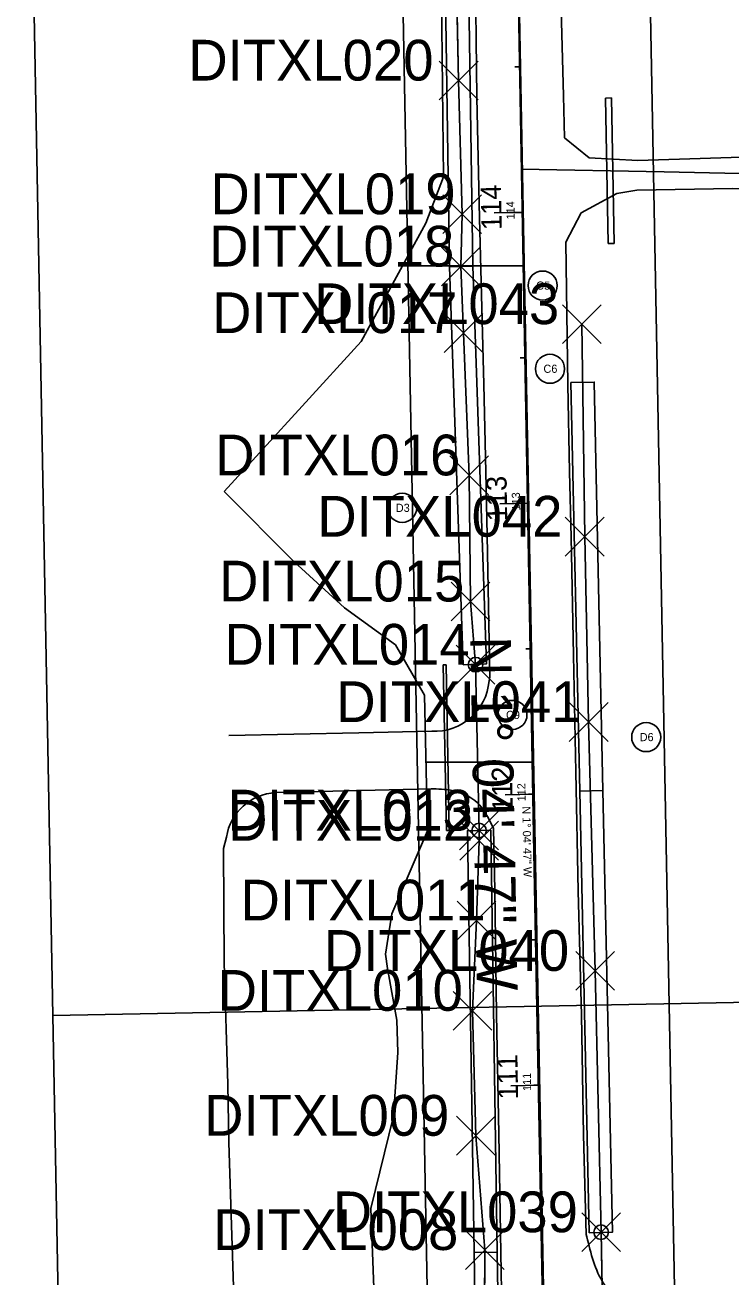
# Model space of a CAD drawing. Extents: x 2287043 to 2296348, y 637947 to 641293.
# Drawn here: x 2287203.9 to 2287446.6, y 639007.3 to 639437.5 of the extents above; entities that cross this region are included whole.
import ezdxf

# ---------------------------------------------------------------- set-up
doc = ezdxf.new("R2010")
doc.units = 0
for name, color, linetype in [('DR_P_Drainage_Area', 7, 'Continuous'), ('DR_P_Storm_Sewer', 7, 'Continuous'), ('GE_X_CL_100', 7, 'Continuous'), ('GE_X_CL_20', 7, 'Continuous'), ('GE_X_CL_50', 7, 'Continuous'), ('GK_Visualization', 7, 'Continuous'), ('RW_P_Prelim_RW', 7, 'Continuous'), ('SC_Scratch11', 7, 'Continuous'), ('SC_Scratch12', 7, 'Continuous'), ('SC_Scratch2', 7, 'Continuous'), ('SC_Scratch4', 7, 'Continuous'), ('SC_Scratch7', 7, 'Continuous'), ('SC_Scratch8', 7, 'Continuous'), ('SC_Scratch9', 7, 'Continuous')]:
    doc.layers.add(name, color=color, linetype=linetype)

msp = doc.modelspace()

# ---------------------------------------------------------------- linework, layer by layer
at = {"layer": 'DR_P_Drainage_Area'}
for p, q in [((2287344.62, 639663.86), (2287347.81, 639385.32)), ((2287378.24, 639184.24), (2287341.77, 639184.24)), ((2287327.5, 638898.94), (2287322.85, 639030.76))]:
    msp.add_line(p, q, dxfattribs=at)
for points in [[(2287365.99, 639861.68), (2287378.81, 639153.12), (2287391.95, 638476.45)], [(2287374.46, 639387.93), (2287423.69, 639387.1), (2287491.39, 639385.61), (2287561.27, 639386.88)], [(2287347.81, 639385.32), (2287341.65, 639369.4), (2287319.48, 639328.73), (2287299.16, 639306.57), (2287272.39, 639277.21)], [(2287331.33, 639224.47), (2287313.69, 639237.21), (2287296.31, 639253.19), (2287272.39, 639277.21)], [(2287342.24, 639160.62), (2287341.3, 639207.22), (2287331.33, 639224.47)], [(2287327.88, 639118.25), (2287330.07, 639132.12), (2287342.24, 639160.62)], [(2287322.85, 639030.76), (2287330.55, 639062.49), (2287332.11, 639084.39), (2287331.79, 639095.57), (2287328.48, 639113.22), (2287327.88, 639118.25)]]:
    msp.add_lwpolyline(points, dxfattribs=at)
at = {"layer": 'DR_P_Storm_Sewer'}
for p, q in [((2287403.48, 639412.42), (2287405.48, 639412.45)), ((2287404.43, 639362.43), (2287403.48, 639412.42)), ((2287406.43, 639362.46), (2287405.48, 639412.45)), ((2287404.43, 639362.43), (2287406.43, 639362.46)), ((2287347.69, 639217.66), (2287348.69, 639217.68)), ((2287348.76, 639160.68), (2287347.69, 639217.66)), ((2287349.76, 639160.7), (2287348.69, 639217.68)), ((2287348.76, 639160.68), (2287349.76, 639160.7))]:
    msp.add_line(p, q, dxfattribs=at)
at = {"layer": 'GE_X_CL_100'}
for p, q in [((2287401.6, 637973.38), (2287357.08, 640335.42)), ((2287375.22, 639373.13), (2287365.22, 639372.94)), ((2287377.1, 639273.15), (2287367.1, 639272.96)), ((2287378.99, 639173.17), (2287368.99, 639172.98)), ((2287380.87, 639073.19), (2287370.87, 639073))]:
    msp.add_line(p, q, dxfattribs=at)
at = {"layer": 'GE_X_CL_20'}
for p, q in [((2287401.6, 637973.38), (2287357.08, 640335.42)), ((2287374.28, 639423.12), (2287372.28, 639423.09)), ((2287375.22, 639373.13), (2287373.22, 639373.1)), ((2287376.16, 639323.14), (2287374.16, 639323.1)), ((2287377.1, 639273.15), (2287375.1, 639273.11)), ((2287378.05, 639223.16), (2287376.05, 639223.12)), ((2287378.99, 639173.17), (2287376.99, 639173.13)), ((2287379.93, 639123.18), (2287377.93, 639123.14)), ((2287380.87, 639073.19), (2287378.87, 639073.15)), ((2287381.81, 639023.2), (2287379.81, 639023.16))]:
    msp.add_line(p, q, dxfattribs=at)
at = {"layer": 'GE_X_CL_50'}
for p, q in [((2287401.6, 637973.38), (2287357.08, 640335.42)), ((2287375.22, 639373.13), (2287370.22, 639373.04)), ((2287375.22, 639373.13), (2287370.22, 639373.04)), ((2287377.1, 639273.15), (2287372.1, 639273.06)), ((2287377.1, 639273.15), (2287372.1, 639273.06)), ((2287378.99, 639173.17), (2287373.99, 639173.07)), ((2287378.99, 639173.17), (2287373.99, 639173.07)), ((2287380.87, 639073.19), (2287375.87, 639073.09)), ((2287380.87, 639073.19), (2287375.87, 639073.09))]:
    msp.add_line(p, q, dxfattribs=at)
at = {"layer": 'GK_Visualization'}
for p, q in [((2287352.98, 639418.42), (2287351.79, 639473.08)), ((2287346.31, 639411.75), (2287359.65, 639425.1)), ((2287346.31, 639425.1), (2287359.65, 639411.75)), ((2287354.17, 639372.48), (2287352.98, 639418.42)), ((2287347.5, 639365.81), (2287360.83, 639379.16)), ((2287347.5, 639379.16), (2287360.83, 639365.81)), ((2287353.72, 639354.51), (2287354.17, 639372.48)), ((2287347.05, 639347.84), (2287360.38, 639361.19)), ((2287347.05, 639361.19), (2287360.38, 639347.84)), ((2287354.63, 639331.64), (2287353.72, 639354.51)), ((2287388.64, 639328.04), (2287401.97, 639341.39)), ((2287388.64, 639341.39), (2287401.97, 639328.04)), ((2287347.96, 639324.97), (2287361.29, 639338.32)), ((2287347.96, 639338.32), (2287361.29, 639324.97)), ((2287356.58, 639282.73), (2287354.63, 639331.64)), ((2287396.32, 639261.68), (2287395.31, 639334.71)), ((2287349.91, 639276.06), (2287363.25, 639289.41)), ((2287349.91, 639289.41), (2287363.25, 639276.06)), ((2287357.05, 639239.4), (2287356.58, 639282.73)), ((2287389.65, 639255), (2287402.99, 639268.35)), ((2287389.65, 639268.35), (2287402.99, 639255)), ((2287397.68, 639197.97), (2287396.32, 639261.68)), ((2287350.38, 639232.73), (2287363.71, 639246.08)), ((2287350.38, 639246.08), (2287363.71, 639232.73)), ((2287358.79, 639217.68), (2287357.05, 639239.4)), ((2287352.13, 639211.01), (2287365.46, 639224.36)), ((2287352.13, 639224.36), (2287365.46, 639211.01)), ((2287360, 639160.7), (2287358.79, 639217.68)), ((2287391.01, 639191.29), (2287404.35, 639204.64)), ((2287391.01, 639204.64), (2287404.35, 639191.29)), ((2287399.93, 639112.47), (2287397.68, 639197.97)), ((2287353.33, 639154.03), (2287366.66, 639167.38)), ((2287353.33, 639167.38), (2287366.66, 639154.03)), ((2287353.39, 639150.51), (2287366.72, 639163.86)), ((2287353.39, 639163.86), (2287366.72, 639150.51)), ((2287360.05, 639157.19), (2287360, 639160.7)), ((2287359.14, 639129.78), (2287360.05, 639157.19)), ((2287352.47, 639123.11), (2287365.81, 639136.46)), ((2287352.47, 639136.46), (2287365.81, 639123.11)), ((2287357.77, 639098.75), (2287359.14, 639129.78)), ((2287393.26, 639105.8), (2287406.6, 639119.15)), ((2287393.26, 639119.15), (2287406.6, 639105.8)), ((2287401.96, 639022.65), (2287399.93, 639112.47)), ((2287351.1, 639092.08), (2287364.44, 639105.43)), ((2287351.1, 639105.43), (2287364.44, 639092.08)), ((2287358.87, 639055.82), (2287357.77, 639098.75)), ((2287352.2, 639049.15), (2287365.53, 639062.5)), ((2287352.2, 639062.5), (2287365.53, 639049.15)), ((2287361.96, 639016.55), (2287358.87, 639055.82)), ((2287395.3, 639015.97), (2287408.63, 639029.32)), ((2287395.3, 639029.32), (2287408.63, 639015.97)), ((2287355.29, 639009.87), (2287368.62, 639023.22)), ((2287355.29, 639023.22), (2287368.62, 639009.87)), ((2287403.46, 638936.65), (2287401.96, 639022.65)), ((2287361.74, 638970.54), (2287361.96, 639016.55))]:
    msp.add_line(p, q, dxfattribs=at)
at = {"layer": 'RW_P_Prelim_RW'}
for p, q in [((2287348.42, 638672.5), (2287326.8, 639819.59)), ((2287433.4, 638674.11), (2287411.84, 639818.25))]:
    msp.add_line(p, q, dxfattribs=at)
at = {"layer": 'SC_Scratch11'}
for points in [[(2287349.86, 639354.56), (2287342.67, 639840.38), (2287350.67, 639840.5), (2287357.86, 639354.68)], [(2287354.57, 639217.68), (2287349.86, 639354.41), (2287357.86, 639354.68), (2287362.56, 639217.96)], [(2287394.6, 639174.25), (2287391.58, 639314.63), (2287399.58, 639314.8), (2287402.6, 639174.42)], [(2287358.28, 639015.66), (2287356, 639160.64), (2287364, 639160.76), (2287366.28, 639015.78)]]:
    msp.add_lwpolyline(points, close=True, dxfattribs=at)
at = {"layer": 'SC_Scratch12'}
msp.add_line((2287375.16, 639354.77), (2287333.67, 639354.77), dxfattribs=at)
at = {"layer": 'SC_Scratch2'}
for points in [[(2287213.53, 639097.15), (2287203.92, 639607.06), (2287533.86, 639613.28), (2287543.47, 639103.37)], [(2287223.14, 638587.24), (2287213.53, 639097.15), (2287543.47, 639103.37), (2287553.08, 638593.46)]]:
    msp.add_lwpolyline(points, close=True, dxfattribs=at)
at = {"layer": 'SC_Scratch4'}
for p, q in [((2287363.72, 639213.43), (2287363.42, 639212.08)), ((2287290.08, 639173.71), (2287314.69, 639174.36)), ((2287314.69, 639174.36), (2287343.52, 639175.02)), ((2287364.53, 639162.41), (2287364.94, 639161.35)), ((2287272.17, 639154.51), (2287273.16, 639158.41)), ((2287396.86, 639021.86), (2287397.08, 639021.08))]:
    msp.add_line(p, q, dxfattribs=at)
for points in [[(2287362.77, 639262.13), (2287362.38, 639283.92), (2287361.7, 639313.93), (2287360.11, 639371.1), (2287359.2, 639412.59), (2287358.64, 639462.65), (2287357.69, 639512.4), (2287356.88, 639563.05), (2287355.9, 639612.32)], [(2287385.25, 639612.29), (2287386.09, 639563.69), (2287386.86, 639511.87), (2287387.65, 639464.13), (2287388.98, 639413.19), (2287389.34, 639398.71)], [(2287414.56, 639390.91), (2287397.81, 639391.91), (2287389.34, 639398.71)], [(2287414.56, 639390.91), (2287464.55, 639392.5), (2287481.49, 639391.88), (2287499.77, 639391.8), (2287508.6, 639391.91), (2287533.21, 639392.12), (2287559.37, 639392.76)], [(2287389.84, 639362.89), (2287395.12, 639372.95), (2287407.35, 639379.58), (2287414.26, 639380.77)], [(2287484.85, 639380.5), (2287472.49, 639380.96), (2287447.25, 639381.27), (2287414.26, 639380.77)], [(2287389.84, 639362.89), (2287390.55, 639314), (2287391.1, 639283.94), (2287391.72, 639261.53)], [(2287362.77, 639262.13), (2287363.72, 639213.43)], [(2287391.72, 639261.53), (2287392.47, 639220.98), (2287393.32, 639180.85), (2287394.08, 639139.83), (2287395.22, 639097.24), (2287395.88, 639056.14), (2287396.86, 639021.86)], [(2287343.76, 639194.79), (2287318.71, 639194.3), (2287273.95, 639193.4)], [(2287364.94, 639161.35), (2287365.38, 639140.22), (2287366.04, 639097.42), (2287366.85, 639056.45), (2287367.51, 639015.53), (2287368.23, 638976.63), (2287368.94, 638936.33), (2287369.74, 638895.15), (2287370.39, 638855.41), (2287370.66, 638843.13)], [(2287272.17, 639154.51), (2287272.32, 639115.21), (2287273.58, 639073.5)], [(2287277.68, 638935.54), (2287277.57, 638940.74), (2287276.27, 638982.52), (2287273.98, 639053.49), (2287273.58, 639073.5)]]:
    msp.add_lwpolyline(points, dxfattribs=at)
for centre, radius, start, end in [((2287344.69, 639213.56), 18.79, 267.1606, 355.5044), ((2287291.04, 639155.65), 18.09, 93.0457, 171.2442)]:
    msp.add_arc(centre, radius, start, end, dxfattribs=at)
for points in [[(2287343.52, 639175.02), (2287350.65, 639174.47), (2287359.42, 639170.18), (2287364.53, 639162.41)], [(2287397.08, 639021.08), (2287402.95, 639004.87), (2287413, 638995.92), (2287427.56, 638992.01)]]:
    msp.add_spline(points, degree=3, dxfattribs=at)
at = {"layer": 'SC_Scratch7'}
for points in [[(2287370.07, 638665.9), (2287367.2, 638718.49), (2287367.44, 638749.32), (2287364.81, 638854.36), (2287362.2, 638897.29), (2287362.51, 638936.53), (2287361.74, 638970.54), (2287361.96, 639016.55), (2287358.87, 639055.82), (2287357.77, 639098.75), (2287359.14, 639129.78), (2287360.05, 639157.19), (2287360, 639160.7), (2287358.79, 639217.68), (2287357.05, 639239.4), (2287356.58, 639282.73), (2287354.63, 639331.64), (2287353.72, 639354.51), (2287354.17, 639372.48), (2287352.98, 639418.42), (2287351.79, 639473.08)], [(2287416.65, 638698.16), (2287417.46, 638727.59), (2287415.72, 638741.9), (2287414.51, 638819.53), (2287412.1, 638875.23), (2287406.67, 638916.45), (2287406.26, 638929.25), (2287403.46, 638936.65), (2287401.96, 639022.65), (2287399.93, 639112.47), (2287397.68, 639197.97), (2287396.32, 639261.68), (2287395.31, 639334.71)]]:
    msp.add_lwpolyline(points, dxfattribs=at)
for centre in [(2287358.79, 639217.68), (2287360, 639160.7), (2287401.96, 639022.65)]:
    msp.add_circle(centre, 2.5, dxfattribs=at)
at = {"layer": 'SC_Scratch8'}
for centre in [(2287381.85, 639347.96), (2287384.39, 639319.38), (2287333.59, 639271.58), (2287371.48, 639200.43), (2287417.47, 639192.8)]:
    msp.add_circle(centre, 5, dxfattribs=at)
at = {"layer": 'SC_Scratch9'}
for points in [[(2287397.86, 639022.48), (2287394.6, 639174.25), (2287402.6, 639174.42), (2287405.86, 639022.65)], [(2287359.46, 638940.67), (2287358.28, 639015.66), (2287366.28, 639015.78), (2287367.46, 638940.79)]]:
    msp.add_lwpolyline(points, close=True, dxfattribs=at)

# ---------------------------------------------------------------- texts
at = {"layer": 'GE_X_CL_100'}
msp.add_text('N 1%%d 04\' 47" W', height=14, rotation=271.0798, dxfattribs=at).set_placement((2287356.96, 639227.29))
at = {"layer": 'GE_X_CL_20'}
for s, rotation, p in [('114', 91.0798, (2287372.26, 639370.72)), ('113', 91.0798, (2287374.15, 639270.69)), ('112', 91.0798, (2287376.03, 639170.74)), ('N 1%%d 04\' 47" W', 271.0798, (2287374.87, 639168.98)), ('111', 91.0798, (2287377.91, 639071.23))]:
    msp.add_text(s, height=2.8, rotation=rotation, dxfattribs=at).set_placement(p)
at = {"layer": 'GE_X_CL_50'}
for s, p in [('114', (2287367.83, 639367.1)), ('114', (2287367.83, 639367.1)), ('113', (2287369.72, 639267.01)), ('113', (2287369.72, 639267.01)), ('112', (2287371.6, 639167.11)), ('112', (2287371.6, 639167.11)), ('111', (2287373.46, 639068.29)), ('111', (2287373.46, 639068.29))]:
    msp.add_text(s, height=7, rotation=91.0798, dxfattribs=at).set_placement(p)
at = {"layer": 'GK_Visualization'}
for s, p in [('DITXL020', (2287260.06, 639418.42)), ('DITXL019', (2287267.64, 639372.48)), ('DITXL018', (2287267.2, 639354.51)), ('DITXL043', (2287303.27, 639334.71)), ('DITXL017', (2287268.22, 639331.64)), ('DITXL016', (2287269.29, 639282.73)), ('DITXL042', (2287304.39, 639261.68)), ('DITXL015', (2287270.64, 639239.4)), ('DITXL014', (2287272.49, 639217.68)), ('DITXL041', (2287310.91, 639197.97)), ('DITXL013', (2287273.59, 639160.7)), ('DITXL012', (2287273.75, 639157.19)), ('DITXL011', (2287278, 639129.78)), ('DITXL040', (2287306.68, 639112.47)), ('DITXL010', (2287270.15, 639098.75)), ('DITXL009', (2287265.5, 639055.82)), ('DITXL039', (2287309.7, 639022.65)), ('DITXL008', (2287268.59, 639016.55))]:
    msp.add_text(s, height=14, dxfattribs=at).set_placement(p)
at = {"layer": 'SC_Scratch8'}
for s, p in [('C5', (2287379.64, 639346.56)), ('C6', (2287382.14, 639317.98)), ('D3', (2287331.38, 639270.18)), ('C9', (2287369.27, 639199.03)), ('D6', (2287415.22, 639191.4))]:
    msp.add_text(s, height=2.8, dxfattribs=at).set_placement(p)

doc.saveas('drawing.dxf')
